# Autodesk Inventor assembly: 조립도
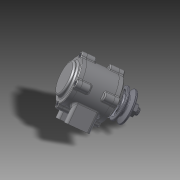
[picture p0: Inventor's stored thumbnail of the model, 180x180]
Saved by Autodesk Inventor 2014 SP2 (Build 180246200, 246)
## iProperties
Created: 2015-03
Part Number: 조립도
Document SubType Name: Weldment
Designer: 2015.02.10
Weld Material: Welded Aluminum-6061
Author: 2015.02.10
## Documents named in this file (11)
- C:\Users\201-12\Desktop\450305v1003\조립도.iam
- C:\Users\201-12\Desktop\450305v1003\1.본체.ipt
- C:\Users\201-12\Desktop\450305v1003\축.ipt
- C:\Users\201-12\Desktop\450305v1003\V벨트풀리.ipt
- C:\Users\201-12\Desktop\450305v1003\커버.ipt
- C:\Users\201-12\Desktop\450305v1003\커버2.ipt
- C:\Users\201-12\Desktop\450305v1003\베어링 6204.ipt
- C:\Users\201-12\Desktop\450305v1003\오일실.ipt
- C:\Users\201-12\Desktop\450305v1003\키(4 x 4 x 12).ipt
- C:\Users\201-12\Desktop\450305v1003\너트 M12x1.25.ipt
- C:\Users\201-12\Desktop\450305v1003\M 4 x 12.ipt
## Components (15 placed, 7 different names)
1. 1.본체:1
2. 그루브 풀리1:1 — 각도:1
3. KS B 2023 6204 - 20 x 47 x 14:1
4. KS B 2023 6204 - 20 x 47 x 14:2
5. KS B 2804 D D - 20 32 8:1
6. KS B 1311 (I) 4 x 4 x 12:1 — 각도:1
7. KS B 1012 클래스 1 일반 - 미터 M12x1.25:1
8. KS B 1003 - 미터 M 4 x 12:1
9. KS B 1003 - 미터 M 4 x 12:2
10. KS B 1003 - 미터 M 4 x 12:3
11. KS B 1003 - 미터 M 4 x 12:4
12. KS B 1003 - 미터 M 4 x 12:5
13. KS B 1003 - 미터 M 4 x 12:6
14. KS B 1003 - 미터 M 4 x 12:7
15. KS B 1003 - 미터 M 4 x 12:8
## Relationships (1: Angle 1)
- 각도:1 [Angle]: 그루브 풀리1:1 ↔ KS B 1311 (I) 4 x 4 x 12:1
